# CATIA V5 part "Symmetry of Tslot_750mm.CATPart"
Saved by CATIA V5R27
Part number: Symmetry of Tslot_750mm
Bounding box of the stored display mesh (mm): x -19.056 to 19.056, y -19.056 to 19.056, z -1524 to -774
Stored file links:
  \\triton.meca.polymtl.ca\usagers\zaoue\profiles\Desktop\varm_ass\structure prismatique\Symmetry of Tslot_750mm.CATPart
  \\triton.meca.polymtl.ca\usagers\zaoue\profiles\Desktop\varm_ass\structure prismatique\Tslot_750mm.CATPart
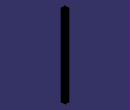
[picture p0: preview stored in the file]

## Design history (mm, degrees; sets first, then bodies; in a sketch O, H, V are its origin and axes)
Body1 (main body)
Body2 "Boss-Extrude1"
  Solid1: linked copy from another document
